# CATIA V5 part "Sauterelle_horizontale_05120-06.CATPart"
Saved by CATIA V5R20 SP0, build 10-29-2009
Part number: Sauterelle_horizontale_05120-06
Nomenclature: 05120-06_1
Source: Unknown
Description: PART-05120-06_1-DESC
Bounding box of the stored display mesh (mm): x -62 to 102.199, y 0 to 71.5, z -28.75 to 6.75
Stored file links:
  E:\Boulot\SeaTech\2eme ANNEE\FabricationAdditive\TP_MOSM_CREM\Projet Sauterelle de serrage\CAO Assemblage Sauterelle\Sauterelle_horizontale_05120-06.CATPart
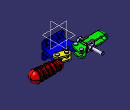
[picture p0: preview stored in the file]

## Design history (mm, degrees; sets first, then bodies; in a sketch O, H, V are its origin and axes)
Body1 "Semelle" (main body)
  Solid1 "05120-06_1": solid without history
Body2 "Bride"
  Solid2 "05120-06_2": solid without history
Body3 "05120-06_3"
  Solid3: solid without history
Body4 "05120-06_4"
  Solid4: solid without history
Body5 "05120-06_6"
  Solid5: solid without history
Body6 "05120-06_7"
  Solid6: solid without history
Body7 "05120-06_8"
  Solid7: solid without history
Body8 "05120-06_9"
  Solid8: solid without history
Body9 "05120-06_10"
  Solid9: solid without history
Body10 "05120-06_11"
  Solid10: solid without history
Body11 "05120-06_12"
  Solid11: solid without history
Body12 "bielle1"
  Solid12 "05120-06_13": solid without history
Body13 "Bielle2"
  Solid13 "05120-06_14": solid without history
Body14 "PoigneeEnrobage"
  Solid14 "05120-06_15": solid without history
